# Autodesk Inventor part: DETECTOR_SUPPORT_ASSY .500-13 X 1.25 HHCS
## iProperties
Shininess: 64.0
Length Units: 11272
Angle Units: 11279
Time Units: 11290
Mass Units: 11286
Length Display Precision: 3
Angle Display Precision: 2
Compacted: True
Part Number: DETECTOR_SUPPORT_ASSY .500-13 X 1.25 HHCS
Document SubType Name: Modeling
Created: 2004-08
Designer: John Blackburn
Material: STAINLESS_STEEL, AUSTENITIC
Manufacturer: Standard
Standards Organization: Custom
Density: 0.0
Volumn: 0.0
Area: 0.0
PropertySet Name: Model Information
Control State: 0
Master: False
Checked Out: False
Author: John Blackburn
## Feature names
1. Base1
